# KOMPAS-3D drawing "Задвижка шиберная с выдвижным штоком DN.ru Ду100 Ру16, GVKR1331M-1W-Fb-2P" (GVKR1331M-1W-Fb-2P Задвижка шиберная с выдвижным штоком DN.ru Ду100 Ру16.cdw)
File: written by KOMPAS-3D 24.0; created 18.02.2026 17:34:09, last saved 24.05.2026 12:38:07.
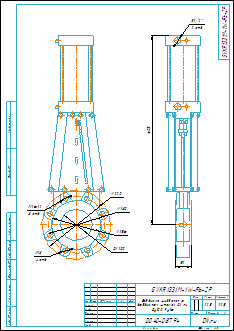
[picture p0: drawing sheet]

Document properties: Автор: R2D2; Форматы листов документа: A3; Полное имя файла: GVKR1331M-1W-Fb-2P Задвижка шиберная с выдвижным штоком DN.ru Ду100 Ру16.m3d; Масса: 12.5; Наименование: Задвижка шиберная с выдвижным штоком DN.ru Ду100 Ру16; Количество листов документа: 1; Примечание: D040-08794

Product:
- Part/product: Задвижка шиберная с выдвижным штоком DN.ru Ду100 Ру16  | designation GVKR1331M-1W-Fb-2P
    Масса: 12.5
    Раздел спецификации: Прочие изделия
    Примечание: D040-08794

Views: Вид 1, Спереди, Проекционный вид 2
Referenced files in E:\Работа\Зайцев\GVKR1331N-2W-Fb-S Задвижка шиберная с выдвижным штоком DN.ru Ду50-300 Ру10\DN50\: GVKR1331N-2W-Fb-S Задвижка шиберная DN.ru Ду50 Ру10.m3d
Referenced files in E:\Работа\Зайцев\GVKR1331M-1W-Fb-2P Задвижка шиберная с выдвижным штоком DN.ru Ду50-300 Ру16-10-6 с пневмоприводом\исходные материалы\DN100\DN100\: GVKR1331M-1W-Fb-2P Задвижка шиберная с выдвижным штоком DN.ru Ду100 Ру16.m3d
Referenced files in E:\Работа\Зайцев\Для компаса\: чертеж DN.ru А3.cdt
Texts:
  GVKR1331M-1W-Fb-2P
  чертеж DN.ru А3.cdt
  Задвижка шиберная с
  выдвижным штоком DN.ru
  Ду100 Ру16
  Задвижка шиберная с выдвижным штоком DN.ru Ду100 Ру16
  GVKR1331M-1W-Fb-2P Задвижка шиберная с выдвижным штоком DN.ru Ду100 Ру16
Dimensions and other numbers on the sheet: 0; 3; 2; 4; 16; 8 отв.; 18; 4 отв.; 220; 180; 156; 100; 2 отв.; 51; 603; 1:2,5; 1; 12,5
